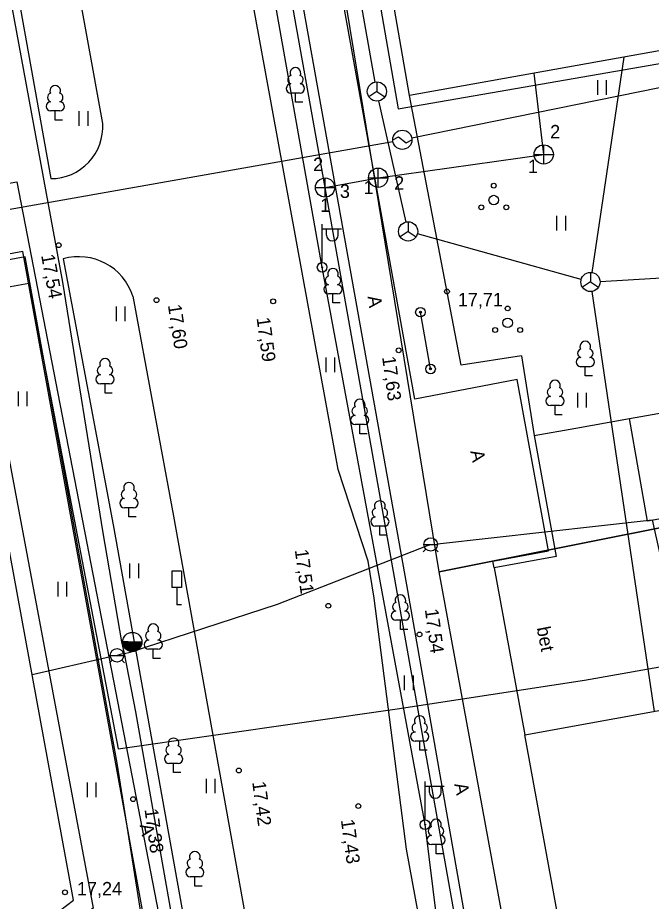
# Model space of a CAD drawing. Extents: x 713540 to 713867, y 6589774 to 6590061.
# Drawn here: x 713667.81 to 713700.77, y 6589963.85 to 6590009.83 of the extents above; entities that cross this region are included whole.
import ezdxf

# ---------------------------------------------------------------- set-up
doc = ezdxf.new("R2010")
doc.units = 0
for name, color, linetype in [('AED', 7, 'Continuous'), ('HALJASTUS', 7, 'Continuous'), ('HOONE', 7, 'Continuous'), ('HOONEDET', 7, 'Continuous'), ('KKAEV', 7, 'Continuous'), ('KORGUS', 7, 'Continuous'), ('KTRASS', 7, 'Continuous'), ('LIIKLUS', 7, 'Continuous'), ('MPKAABEL', 7, 'Continuous'), ('POST', 7, 'Continuous'), ('PUU', 7, 'Continuous'), ('SIKAEV', 7, 'Continuous'), ('SITRASS', 7, 'Continuous'), ('TEE', 7, 'Continuous'), ('TORU NR', 7, 'Continuous'), ('VKAEV', 7, 'Continuous'), ('VTRASS', 7, 'Continuous'), ('Слой 1', 7, 'Continuous')]:
    doc.layers.add(name, color=color, linetype=linetype)

msp = doc.modelspace()

# ---------------------------------------------------------------- linework, layer by layer
at = {"layer": 'AED'}
for points in [[(713694.019, 6589992.235), (713690.884, 6589991.744), (713688.188, 6590005.782)], [(713694.019, 6589992.235), (713694.676, 6589988.089), (713695.825, 6589981.802), (713692.595, 6589981.212), (713693.062, 6589978.657)], [(713694.676, 6589988.089), (713696.851, 6589988.472), (713699.632, 6589988.973)]]:
    msp.add_lwpolyline(points, dxfattribs=at)
at = {"layer": 'HALJASTUS'}
for p, q in [((713697.966, 6590006.578), (713697.966, 6590005.817)), ((713698.421, 6590006.578), (713698.421, 6590005.817)), ((713670.995, 6590004.969), (713670.995, 6590004.208)), ((713671.45, 6590004.969), (713671.45, 6590004.208)), ((713695.847, 6589999.521), (713695.847, 6589998.76)), ((713696.302, 6589999.521), (713696.302, 6589998.76)), ((713672.924, 6589994.798), (713672.924, 6589994.036)), ((713673.379, 6589994.798), (713673.379, 6589994.036)), ((713683.834, 6589992.14), (713683.834, 6589991.379)), ((713684.289, 6589992.14), (713684.289, 6589991.379)), ((713667.826, 6589990.372), (713667.826, 6589989.611)), ((713668.281, 6589990.372), (713668.281, 6589989.611)), ((713696.934, 6589990.309), (713696.934, 6589989.548)), ((713697.389, 6589990.309), (713697.389, 6589989.548)), ((713673.628, 6589981.428), (713673.628, 6589980.667)), ((713674.084, 6589981.428), (713674.084, 6589980.667)), ((713669.895, 6589980.468), (713669.895, 6589979.707)), ((713670.351, 6589980.468), (713670.351, 6589979.707)), ((713687.919, 6589975.606), (713687.919, 6589974.845)), ((713688.374, 6589975.606), (713688.374, 6589974.845)), ((713677.606, 6589970.235), (713677.606, 6589969.474)), ((713678.061, 6589970.235), (713678.061, 6589969.474)), ((713671.425, 6589970.031), (713671.425, 6589969.27)), ((713671.88, 6589970.031), (713671.88, 6589969.27))]:
    msp.add_line(p, q, dxfattribs=at)
for centre, radius in [((713692.576, 6590001.085), 0.125), ((713692.576, 6590000.335), 0.25), ((713691.926, 6589999.96), 0.125), ((713693.226, 6589999.96), 0.125), ((713693.299, 6589994.701), 0.125), ((713693.299, 6589993.951), 0.25), ((713692.649, 6589993.576), 0.125), ((713693.949, 6589993.576), 0.125)]:
    msp.add_circle(centre, radius, dxfattribs=at)
at = {"layer": 'HOONE'}
for p, q in [((713687.32, 6590003.473), (713687.62, 6590003.623)), ((713687.62, 6590003.623), (713688.02, 6590003.323)), ((713688.02, 6590003.323), (713688.32, 6590003.473))]:
    msp.add_line(p, q, dxfattribs=at)
for points in [[(713703.989, 6590008.604), (713688.188, 6590005.782), (713684.27, 6590028.353), (713700.164, 6590031.112), (713703.989, 6590008.604)], [(713688.31, 6590003.572), (713701.203, 6590006.196)], [(713641.66, 6589995.12), (713651.08, 6589996.88), (713659.244, 6589998.419), (713687.328, 6590003.385)], [(713665.097, 6589994.469), (713654.36, 6589992.62), (713659, 6589966.87), (713655.32, 6589963.97), (713631.86, 6589975.579), (713626.949, 6589965.568), (713655.111, 6589952.011), (713657.717, 6589953.998), (713658.827, 6589952.543), (713664.692, 6589957.048), (713664.664, 6589957.055), (713669.225, 6589960.582), (713668.167, 6589961.969), (713670.71, 6589963.909), (713665.097, 6589994.469)], [(713699.632, 6589988.973), (713708.573, 6589990.543), (713709.518, 6589985.205), (713700.57, 6589983.634), (713699.632, 6589988.973)], [(713700.081, 6589942.962), (713699.945, 6589943.703), (713699.469, 6589943.616), (713699.43, 6589943.831), (713694.186, 6589972.51), (713708.231, 6589975.063), (713712.15, 6589954.52), (713714.85, 6589952.78), (713720.42, 6589962.79), (713724.48, 6589971.41), (713726.078, 6589970.623), (713726.102, 6589970.646), (713737.433, 6589964.699), (713721.341, 6589934.036), (713720.864, 6589934.287), (713720.463, 6589933.523)]]:
    msp.add_lwpolyline(points, dxfattribs=at)
msp.add_circle((713687.82, 6590003.473), 0.5, dxfattribs=at)
at = {"layer": 'HOONEDET'}
for points in [[(713702.7, 6590022.49), (713701.04, 6590031.975), (713683.46, 6590028.923), (713687.599, 6590005.08), (713705.008, 6590008.102), (713703.29, 6590019.02)], [(713654.365, 6589993.337), (713665.759, 6589995.354), (713671.737, 6589963.499), (713669.522, 6589961.81), (713670.612, 6589960.382), (713665.868, 6589956.768), (713665.7, 6589956.808), (713658.611, 6589951.238), (713657.507, 6589952.685), (713655.117, 6589950.862), (713625.629, 6589965.327), (713631.231, 6589977.05), (713635.106, 6589975.077), (713639.12, 6589973.07)]]:
    msp.add_lwpolyline(points, dxfattribs=at)
at = {"layer": 'KKAEV'}
for p, q in [((713695.175, 6590002.211), (713695.175, 6590003.211)), ((713694.675, 6590002.711), (713695.675, 6590002.711)), ((713686.557, 6590000.999), (713686.557, 6590001.999)), ((713683.799, 6590000.487), (713683.799, 6590001.487)), ((713686.057, 6590001.499), (713687.057, 6590001.499)), ((713683.299, 6590000.987), (713684.299, 6590000.987))]:
    msp.add_line(p, q, dxfattribs=at)
for centre in [(713695.175, 6590002.711), (713686.557, 6590001.499), (713683.799, 6590000.987)]:
    msp.add_circle(centre, 0.5, dxfattribs=at)
at = {"layer": 'KORGUS'}
for centre in [(713669.94, 6589997.99), (713690.14, 6589995.58), (713675.03, 6589995.13), (713681.1, 6589995.07), (713687.63, 6589992.52), (713683.97, 6589979.23), (713688.71, 6589977.74), (713679.31, 6589970.66), (713673.81, 6589969.17), (713685.53, 6589968.81), (713670.27, 6589964.32)]:
    msp.add_circle(centre, 0.125, dxfattribs=at)
at = {"layer": 'KTRASS'}
for p, q in [((713683.799, 6590000.987), (713678.174, 6590032.691)), ((713695.175, 6590002.711), (713694.669, 6590006.94)), ((713686.557, 6590001.499), (713695.175, 6590002.711)), ((713683.799, 6590000.987), (713686.557, 6590001.499))]:
    msp.add_line(p, q, dxfattribs=at)
at = {"layer": 'LIIKLUS'}
msp.add_line((713689.286, 6589991.551), (713688.761, 6589994.505), dxfattribs=at)
for points in [[(713675.829, 6589981.03), (713675.829, 6589980.18)], [(713676.329, 6589981.03), (713675.829, 6589981.03)], [(713676.329, 6589981.03), (713676.329, 6589980.18)], [(713676.329, 6589980.18), (713675.829, 6589980.18)], [(713676.079, 6589980.18), (713676.079, 6589979.28)], [(713676.329, 6589979.28), (713676.079, 6589979.28)]]:
    msp.add_lwpolyline(points, dxfattribs=at)
for centre, radius in [((713688.761, 6589994.505), 0.25), ((713688.761, 6589994.505), 0.05), ((713689.286, 6589991.551), 0.25), ((713689.286, 6589991.551), 0.05)]:
    msp.add_circle(centre, radius, dxfattribs=at)
at = {"layer": 'MPKAABEL'}
for points in [[(713692.718, 6589944.775), (713692.321, 6589946.558), (713690.066, 6589959.298), (713688.999, 6589967.843), (713683.646, 6589996.839), (713676.43, 6590037.515), (713672.265, 6590060.636)], [(713668.156, 6589956.222), (713674.47, 6589961.65), (713672.98, 6589971.05), (713668.19, 6589997.38), (713658.812, 6589995.642)], [(713659.015, 6589994.315), (713668.392, 6589996.01), (713673.043, 6589971.78), (713687.552, 6589973.876), (713697.295, 6589975.361), (713709.25, 6589977.48), (713710.11, 6589973.77), (713708.57, 6589973.51)]]:
    msp.add_lwpolyline(points, dxfattribs=at)
at = {"layer": 'POST'}
for p, q in [((713683.646, 6589997.089), (713683.646, 6589999.089)), ((713683.646, 6589998.839), (713684.646, 6589998.839)), ((713683.872, 6589998.518), (713683.872, 6589998.839)), ((713684.485, 6589998.518), (713684.485, 6589998.839)), ((713688.999, 6589968.093), (713688.999, 6589970.093)), ((713688.999, 6589969.843), (713689.999, 6589969.843)), ((713689.226, 6589969.522), (713689.226, 6589969.843)), ((713689.838, 6589969.522), (713689.838, 6589969.843))]:
    msp.add_line(p, q, dxfattribs=at)
for centre, radius in [((713683.646, 6589996.839), 0.25), ((713683.646, 6589996.839), 0.0234), ((713688.999, 6589967.843), 0.25), ((713688.999, 6589967.843), 0.0234)]:
    msp.add_circle(centre, radius, dxfattribs=at)
for centre in [(713684.179, 6589998.518), (713689.532, 6589969.522)]:
    msp.add_arc(centre, 0.306, 180, 0, dxfattribs=at)
at = {"layer": 'PUU'}
for p, q in [((713682.497, 6590005.905), (713682.017, 6590005.905)), ((713682.257, 6590005.43), (713682.257, 6590005.905)), ((713682.637, 6590005.43), (713682.257, 6590005.43)), ((713670, 6590004.975), (713669.52, 6590004.975)), ((713669.76, 6590004.5), (713669.76, 6590004.975)), ((713670.14, 6590004.5), (713669.76, 6590004.5)), ((713684.451, 6589995.458), (713683.971, 6589995.458)), ((713684.211, 6589994.983), (713684.211, 6589995.458)), ((713684.591, 6589994.983), (713684.211, 6589994.983)), ((713697.576, 6589991.669), (713697.096, 6589991.669)), ((713697.336, 6589991.194), (713697.336, 6589991.669)), ((713697.716, 6589991.194), (713697.336, 6589991.194)), ((713672.591, 6589990.771), (713672.111, 6589990.771)), ((713672.351, 6589990.296), (713672.351, 6589990.771)), ((713672.731, 6589990.296), (713672.351, 6589990.296)), ((713696.002, 6589989.646), (713695.522, 6589989.646)), ((713695.762, 6589989.171), (713695.762, 6589989.646)), ((713696.142, 6589989.171), (713695.762, 6589989.171)), ((713685.842, 6589988.659), (713685.362, 6589988.659)), ((713685.602, 6589988.184), (713685.602, 6589988.659)), ((713685.982, 6589988.184), (713685.602, 6589988.184)), ((713673.836, 6589984.328), (713673.356, 6589984.328)), ((713673.596, 6589983.853), (713673.596, 6589984.328)), ((713673.976, 6589983.853), (713673.596, 6589983.853)), ((713686.89, 6589983.373), (713686.41, 6589983.373)), ((713686.65, 6589982.898), (713686.65, 6589983.373)), ((713687.03, 6589982.898), (713686.65, 6589982.898)), ((713687.958, 6589978.476), (713687.478, 6589978.476)), ((713687.718, 6589978.001), (713687.718, 6589978.476)), ((713688.098, 6589978.001), (713687.718, 6589978.001)), ((713675.099, 6589976.968), (713674.619, 6589976.968)), ((713674.859, 6589976.493), (713674.859, 6589976.968)), ((713675.239, 6589976.493), (713674.859, 6589976.493)), ((713688.965, 6589972.188), (713688.485, 6589972.188)), ((713688.725, 6589971.713), (713688.725, 6589972.188)), ((713689.105, 6589971.713), (713688.725, 6589971.713)), ((713676.156, 6589971.027), (713675.676, 6589971.027)), ((713675.916, 6589970.552), (713675.916, 6589971.027)), ((713676.296, 6589970.552), (713675.916, 6589970.552)), ((713689.812, 6589966.805), (713689.332, 6589966.805)), ((713689.572, 6589966.33), (713689.572, 6589966.805)), ((713689.952, 6589966.33), (713689.572, 6589966.33)), ((713677.265, 6589965.125), (713676.785, 6589965.125)), ((713677.025, 6589964.65), (713677.025, 6589965.125)), ((713677.405, 6589964.65), (713677.025, 6589964.65))]:
    msp.add_line(p, q, dxfattribs=at)
for centre, radius, start, end in [((713682.257, 6590006.95), 0.277, 332.5799, 207.4201), ((713682.087, 6590006.602), 0.233, 109.0217, 253.1415), ((713682.428, 6590006.602), 0.233, 286.8508, 70.9859), ((713669.76, 6590006.02), 0.277, 332.5799, 207.4201), ((713682.02, 6590006.142), 0.238, 90.0016, 269.3953), ((713682.495, 6590006.142), 0.238, 270.6047, 89.9984), ((713669.59, 6590005.672), 0.233, 109.0217, 253.1415), ((713669.93, 6590005.672), 0.233, 286.8508, 70.9859), ((713669.523, 6590005.212), 0.238, 90.0016, 269.3953), ((713669.997, 6590005.212), 0.238, 270.6047, 89.9984), ((713684.211, 6589996.503), 0.277, 332.5799, 207.4201), ((713684.041, 6589996.156), 0.233, 109.0217, 253.1415), ((713684.381, 6589996.156), 0.233, 286.8508, 70.9859), ((713683.973, 6589995.696), 0.238, 90.0016, 269.3953), ((713684.448, 6589995.696), 0.238, 270.6047, 89.9984), ((713697.336, 6589992.714), 0.277, 332.5799, 207.4201), ((713697.166, 6589992.367), 0.233, 109.0217, 253.1415), ((713697.506, 6589992.367), 0.233, 286.8508, 70.9859), ((713672.351, 6589991.816), 0.277, 332.5799, 207.4201), ((713697.099, 6589991.907), 0.238, 90.0016, 269.3953), ((713697.573, 6589991.907), 0.238, 270.6047, 89.9984), ((713672.18, 6589991.468), 0.233, 109.0217, 253.1415), ((713672.521, 6589991.468), 0.233, 286.8508, 70.9859), ((713672.113, 6589991.008), 0.238, 90.0016, 269.3953), ((713672.588, 6589991.008), 0.238, 270.6047, 89.9984), ((713695.762, 6589990.691), 0.277, 332.5799, 207.4201), ((713695.592, 6589990.344), 0.233, 109.0217, 253.1415), ((713695.932, 6589990.344), 0.233, 286.8508, 70.9859), ((713685.602, 6589989.704), 0.277, 332.5799, 207.4201), ((713695.525, 6589989.884), 0.238, 90.0016, 269.3953), ((713696, 6589989.884), 0.238, 270.6047, 89.9984), ((713685.432, 6589989.357), 0.233, 109.0217, 253.1415), ((713685.772, 6589989.357), 0.233, 286.8508, 70.9859), ((713685.365, 6589988.897), 0.238, 90.0016, 269.3953), ((713685.84, 6589988.897), 0.238, 270.6047, 89.9984), ((713673.596, 6589985.373), 0.277, 332.5799, 207.4201), ((713673.426, 6589985.026), 0.233, 109.0217, 253.1415), ((713673.766, 6589985.026), 0.233, 286.8508, 70.9859), ((713673.358, 6589984.566), 0.238, 90.0016, 269.3953), ((713673.833, 6589984.566), 0.238, 270.6047, 89.9984), ((713686.65, 6589984.418), 0.277, 332.5799, 207.4201), ((713686.48, 6589984.071), 0.233, 109.0217, 253.1415), ((713686.82, 6589984.071), 0.233, 286.8508, 70.9859), ((713686.412, 6589983.611), 0.238, 90.0016, 269.3953), ((713686.887, 6589983.611), 0.238, 270.6047, 89.9984), ((713687.718, 6589979.521), 0.277, 332.5799, 207.4201), ((713687.48, 6589978.713), 0.238, 90.0016, 269.3953), ((713687.548, 6589979.173), 0.233, 109.0217, 253.1415), ((713687.888, 6589979.173), 0.233, 286.8508, 70.9859), ((713687.955, 6589978.713), 0.238, 270.6047, 89.9984), ((713674.859, 6589978.013), 0.277, 332.5799, 207.4201), ((713674.689, 6589977.666), 0.233, 109.0217, 253.1415), ((713675.029, 6589977.666), 0.233, 286.8508, 70.9859), ((713674.621, 6589977.206), 0.238, 90.0016, 269.3953), ((713675.096, 6589977.206), 0.238, 270.6047, 89.9984), ((713688.725, 6589973.233), 0.277, 332.5799, 207.4201), ((713688.555, 6589972.886), 0.233, 109.0217, 253.1415), ((713688.895, 6589972.886), 0.233, 286.8508, 70.9859), ((713688.488, 6589972.426), 0.238, 90.0016, 269.3953), ((713688.963, 6589972.426), 0.238, 270.6047, 89.9984), ((713675.916, 6589972.072), 0.277, 332.5799, 207.4201), ((713675.746, 6589971.724), 0.233, 109.0217, 253.1415), ((713676.086, 6589971.724), 0.233, 286.8508, 70.9859), ((713675.678, 6589971.264), 0.238, 90.0016, 269.3953), ((713676.153, 6589971.264), 0.238, 270.6047, 89.9984), ((713689.572, 6589967.85), 0.277, 332.5799, 207.4201), ((713689.402, 6589967.502), 0.233, 109.0217, 253.1415), ((713689.742, 6589967.502), 0.233, 286.8508, 70.9859), ((713689.335, 6589967.042), 0.238, 90.0016, 269.3953), ((713689.81, 6589967.042), 0.238, 270.6047, 89.9984), ((713677.025, 6589966.17), 0.277, 332.5799, 207.4201), ((713676.855, 6589965.822), 0.233, 109.0217, 253.1415), ((713677.195, 6589965.822), 0.233, 286.8508, 70.9859), ((713676.787, 6589965.362), 0.238, 90.0016, 269.3953), ((713677.262, 6589965.362), 0.238, 270.6047, 89.9984)]:
    msp.add_arc(centre, radius, start, end, dxfattribs=at)
at = {"layer": 'SIKAEV'}
for p, q in [((713686.494, 6590006.485), (713686.494, 6590005.985)), ((713686.494, 6590005.985), (713686.079, 6590005.71)), ((713686.494, 6590005.985), (713686.909, 6590005.71)), ((713688.119, 6589999.207), (713688.119, 6589998.707)), ((713688.119, 6589998.707), (713687.704, 6589998.432)), ((713688.119, 6589998.707), (713688.534, 6589998.432)), ((713697.606, 6589996.577), (713697.606, 6589996.077)), ((713697.606, 6589996.077), (713697.191, 6589995.802)), ((713697.606, 6589996.077), (713698.021, 6589995.802))]:
    msp.add_line(p, q, dxfattribs=at)
for centre in [(713686.494, 6590005.985), (713688.119, 6589998.707), (713697.606, 6589996.077)]:
    msp.add_circle(centre, 0.5, dxfattribs=at)
at = {"layer": 'SITRASS'}
for points in [[(713686.407, 6590006.478), (713676.816, 6590060.636)], [(713699.349, 6590007.775), (713697.68, 6589996.572)], [(713688.01, 6589999.195), (713686.603, 6590005.497)], [(713697.125, 6589996.211), (713688.6, 6589998.573)], [(713698.106, 6589996.106), (713704.202, 6589996.458), (713704.199, 6589996.445), (713718.88, 6589997.31)], [(713697.679, 6589995.582), (713698.548, 6589989.704), (713700.921, 6589973.734)]]:
    msp.add_lwpolyline(points, dxfattribs=at)
at = {"layer": 'TEE'}
msp.add_line((713691.841, 6589955.837), (713683.799, 6590000.987), dxfattribs=at)
for points in [[(713658.871, 6590060.636), (713662.701, 6590039.517), (713669.529, 6590001.451)], [(713672.229, 6590004.328), (713665.804, 6590039.691), (713661.981, 6590060.636)], [(713692.595, 6589981.212), (713692.532, 6589981.556), (713695.416, 6589982.083), (713693.785, 6589991.005), (713688.468, 6589989.986), (713680.98, 6590031.537)], [(713691.7, 6589959.557), (713688.046, 6589980.323), (713678.974, 6590031.096)], [(713689.318, 6589959.578), (713688.035, 6589966.571), (713686.357, 6589979.631), (713686.045, 6589981.554), (713684.475, 6589986.323), (713676.697, 6590028.946)], [(713674.64, 6589955.464), (713675.571, 6589956.424), (713670.734, 6589983.028), (713668.075, 6589997.658), (713664.505, 6589997.008), (713658.749, 6589996.047), (713653.94, 6589995.227), (713654.36, 6589992.62)], [(713670.167, 6589997.275), (713672.773, 6589983.433), (713677.657, 6589956.164)], [(713673.789, 6589995.34), (713675.917, 6589983.899), (713680.636, 6589957.612)], [(713693.062, 6589978.657), (713694.186, 6589972.51)]]:
    msp.add_lwpolyline(points, dxfattribs=at)
for centre, radius, start, end in [((713669.529, 6590004.156), 2.705, 270, 3.6377), ((713670.988, 6589994.453), 2.939, 17.5642, 106.2247)]:
    msp.add_arc(centre, radius, start, end, dxfattribs=at)
at = {"layer": 'VKAEV'}
for p, q in [((713689.048, 6589982.174), (713688.908, 6589982.034)), ((713688.945, 6589982.421), (713689.645, 6589982.421)), ((713689.542, 6589982.174), (713689.682, 6589982.034)), ((713673.27, 6589977.348), (713674.27, 6589977.348)), ((713672.626, 6589976.65), (713673.326, 6589976.65)), ((713672.729, 6589976.403), (713672.589, 6589976.263)), ((713673.224, 6589976.403), (713673.363, 6589976.263))]:
    msp.add_line(p, q, dxfattribs=at)
for centre, radius in [((713689.295, 6589982.421), 0.35), ((713673.77, 6589977.348), 0.5), ((713672.976, 6589976.65), 0.35)]:
    msp.add_circle(centre, radius, dxfattribs=at)
for radius in [0.483, 0.468, 0.45, 0.435, 0.418, 0.403, 0.386, 0.371, 0.354, 0.339, 0.321, 0.306, 0.289, 0.274, 0.257, 0.242, 0.224, 0.209, 0.192, 0.177, 0.16, 0.145, 0.127, 0.112, 0.0951, 0.0801, 0.0628, 0.0478, 0.0328, 0.0178]:
    msp.add_arc((713673.77, 6589977.348), radius, 180, 0, dxfattribs=at)
at = {"layer": 'VTRASS'}
for points in [[(713684.308, 6589921.181), (713683.129, 6589927.373), (713681.203, 6589936.836), (713678.244, 6589950.963), (713676.229, 6589960.85), (713673.946, 6589973.712), (713673.362, 6589976.754), (713673.233, 6589977.362), (713672.25, 6589983.027), (713670.156, 6589996.06), (713667.268, 6590011.807), (713664.478, 6590027.857), (713664.208, 6590029.493), (713663.195, 6590035.091), (713660.78, 6590048.281), (713658.62, 6590060.636)], [(713689.643, 6589982.46), (713700.819, 6589983.706), (713702.84, 6589974.61)], [(713673.362, 6589976.754), (713673.651, 6589976.815), (713681.323, 6589979.31), (713689.125, 6589982.365), (713689.293, 6589982.42)], [(713673.233, 6589977.362), (713673.369, 6589977.384), (713673.767, 6589977.353)], [(713673.362, 6589976.754), (713673.144, 6589976.69), (713672.976, 6589976.65)], [(713672.635, 6589976.572), (713668.557, 6589975.629)]]:
    msp.add_lwpolyline(points, dxfattribs=at)
at = {"layer": 'Слой 1'}
for points in [[(713713.11, 6590039.08), (713713.69, 6590035.37), (713718.88, 6589999.87), (713712.56, 6589991.28), (713713.13, 6589989.8), (713701.84, 6589988.96), (713702.78, 6589983.59), (713689.74, 6589981), (713681.15, 6590033.42)], [(713667.77, 6590001.29), (713675.57, 6589961), (713658.19, 6589946.81), (713619.46, 6589962.4), (713633.01, 6589995.13)], [(713689.74, 6589981), (713702.78, 6589983.59), (713701.84, 6589988.96), (713713.13, 6589989.8), (713713.92, 6589985.29), (713742.5, 6589970.55), (713718.97, 6589926.81), (713697.63, 6589938.02)]]:
    msp.add_lwpolyline(points, close=True, dxfattribs=at)

# ---------------------------------------------------------------- texts
at = {"layer": 'HOONEDET'}
msp.add_text('bet', height=0.7, rotation=280.9721, dxfattribs=at).set_placement((713694.803, 6589978.083))
at = {"layer": 'KORGUS'}
for s, rotation, p in [('17,54', 280.3487, (713669.023, 6589997.461)), ('17,60', 278.5519, (713675.619, 6589994.866)), ('17,59', 277.7119, (713680.233, 6589994.2)), ('17,63', 277.7119, (713686.763, 6589992.17)), ('17,51', 277.7119, (713682.221, 6589982.134)), ('17,54', 277.7119, (713688.987, 6589979.036)), ('17,42', 277.7119, (713680.006, 6589970.052)), ('17,38', 277.7119, (713674.403, 6589968.64)), ('17,43', 277.7119, (713684.619, 6589968.084))]:
    msp.add_text(s, height=0.7, rotation=rotation, dxfattribs=at).set_placement(p)
for s, p in [('17,71', (713690.707, 6589994.81)), ('17,24', (713670.894, 6589964.16))]:
    msp.add_text(s, height=0.7, dxfattribs=at).set_placement(p)
at = {"layer": 'TEE'}
for rotation, p in [(278.5485, (713686.007, 6589995.318)), (281.7487, (713691.349, 6589987.267)), (281.6245, (713690.518, 6589969.949)), (281.8363, (713674.149, 6589967.819))]:
    msp.add_text('A', height=0.7, rotation=rotation, dxfattribs=at).set_placement(p)
at = {"layer": 'TORU NR'}
for s, p in [('2', (713695.509, 6590003.544)), ('2', (713683.176, 6590001.845)), ('1', (713694.356, 6590001.738)), ('2', (713687.393, 6590000.874)), ('3', (713684.571, 6590000.449)), ('1', (713685.8, 6590000.646)), ('1', (713683.547, 6589999.721))]:
    msp.add_text(s, height=0.7, dxfattribs=at).set_placement(p)

doc.saveas('drawing.dxf')
